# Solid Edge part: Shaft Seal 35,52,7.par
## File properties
Title: Shaft Seal 35,52,7
Author: Dan
Comments: Thys Du Plessis        Panacea   9742180  Desmopan 385S      0.8 % Shrinkage      X 1.008  85 Shore A
Template: Normal.par
Last saved by: Dan
Revision: 21
Application: Solid Edge
Material: polyurathane
Density: 1 kg/dm^3
Accuracy: 0.99
Document Number: P52-008
Project Name: Piston Pump P52
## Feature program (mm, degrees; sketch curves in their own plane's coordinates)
sketch for "unnamed RevolvedProtrusion 1" plane through (0, 0, 0) normal (0, 0, 1) x-axis (1, 0, 0)
  line (7, 26.1726) -> (7, 24.2085)
  line (7, 24.2085) -> (2.8, 22.25)
  line (2.8, 22.25) -> (2.8, 21.25)
  line (7, 19.2915) -> (2.8, 21.25)
  line (7, 19.2915) -> (7, 17.3274)
  line (6, 16.75) -> (7, 17.3274)
  line (3, 17.65) -> (6, 16.75)
  line (0, 17.65) -> (3, 17.65)
  line (0, 17.65) -> (0, 25.85)
  line (0, 25.85) -> (3, 25.85)
  line (3, 25.85) -> (6, 26.75)
  line (6, 26.75) -> (7, 26.1726)
  dimension (linear) = 2.8
  dimension (linear) = 7
  dimension (linear) = 7
revolve "unnamed RevolvedProtrusion 1" add full turn 360 deg
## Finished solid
Body 1: solid body, 12 faces, 12 edges, 0 vertices.
  Faces by surface: cone 6, plane 4, cylinder 2
  Edges by curve: circle 12
Bounding box of the edges (mm): 7.000 x 53.500 x 53.500, from (0, -26.75, -26.75) to (7, 26.75, 26.75).
Cylindrical faces by radius (mm): R17.65 x1, R25.85 x1
Conical faces (half-angle, radius in mm at the cone's reference point): 16.6992 deg R16.75 x1, 16.6992 deg R25.85 x1, 25 deg R21.25 x1, 25 deg R24.2085 x1, 30 deg R17.3274 x1, 30 deg R26.75 x1
Planar faces by outward normal: +x 3, -x 1
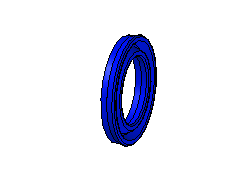
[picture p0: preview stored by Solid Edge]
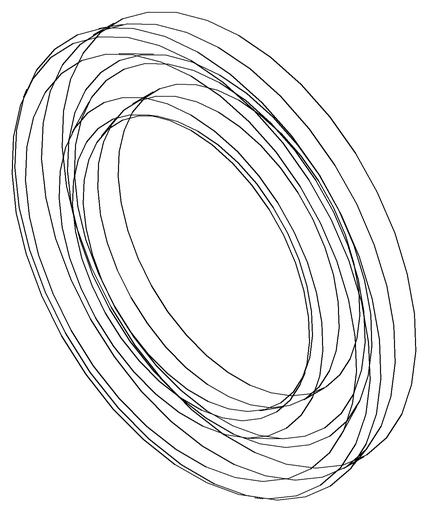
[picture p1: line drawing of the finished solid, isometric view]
